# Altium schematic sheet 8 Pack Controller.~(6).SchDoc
size B; PageSetup: Record=PageOptions|CenterHorizontal=True|CenterVertical=True|PrintScale=1.09|XCorrection=1.00|YCorrection=1.00|PrintKind=0|BorderSize=5000000|LeftOffset=0|BottomOffset=0|Orientation=2|PaperLength=1000|PaperWidth=1000|Scale=100|PaperSource=15|PrintQuality=600|MediaType=1|DitherType=10|PaperKind=11x17|PrintScaleMode=1
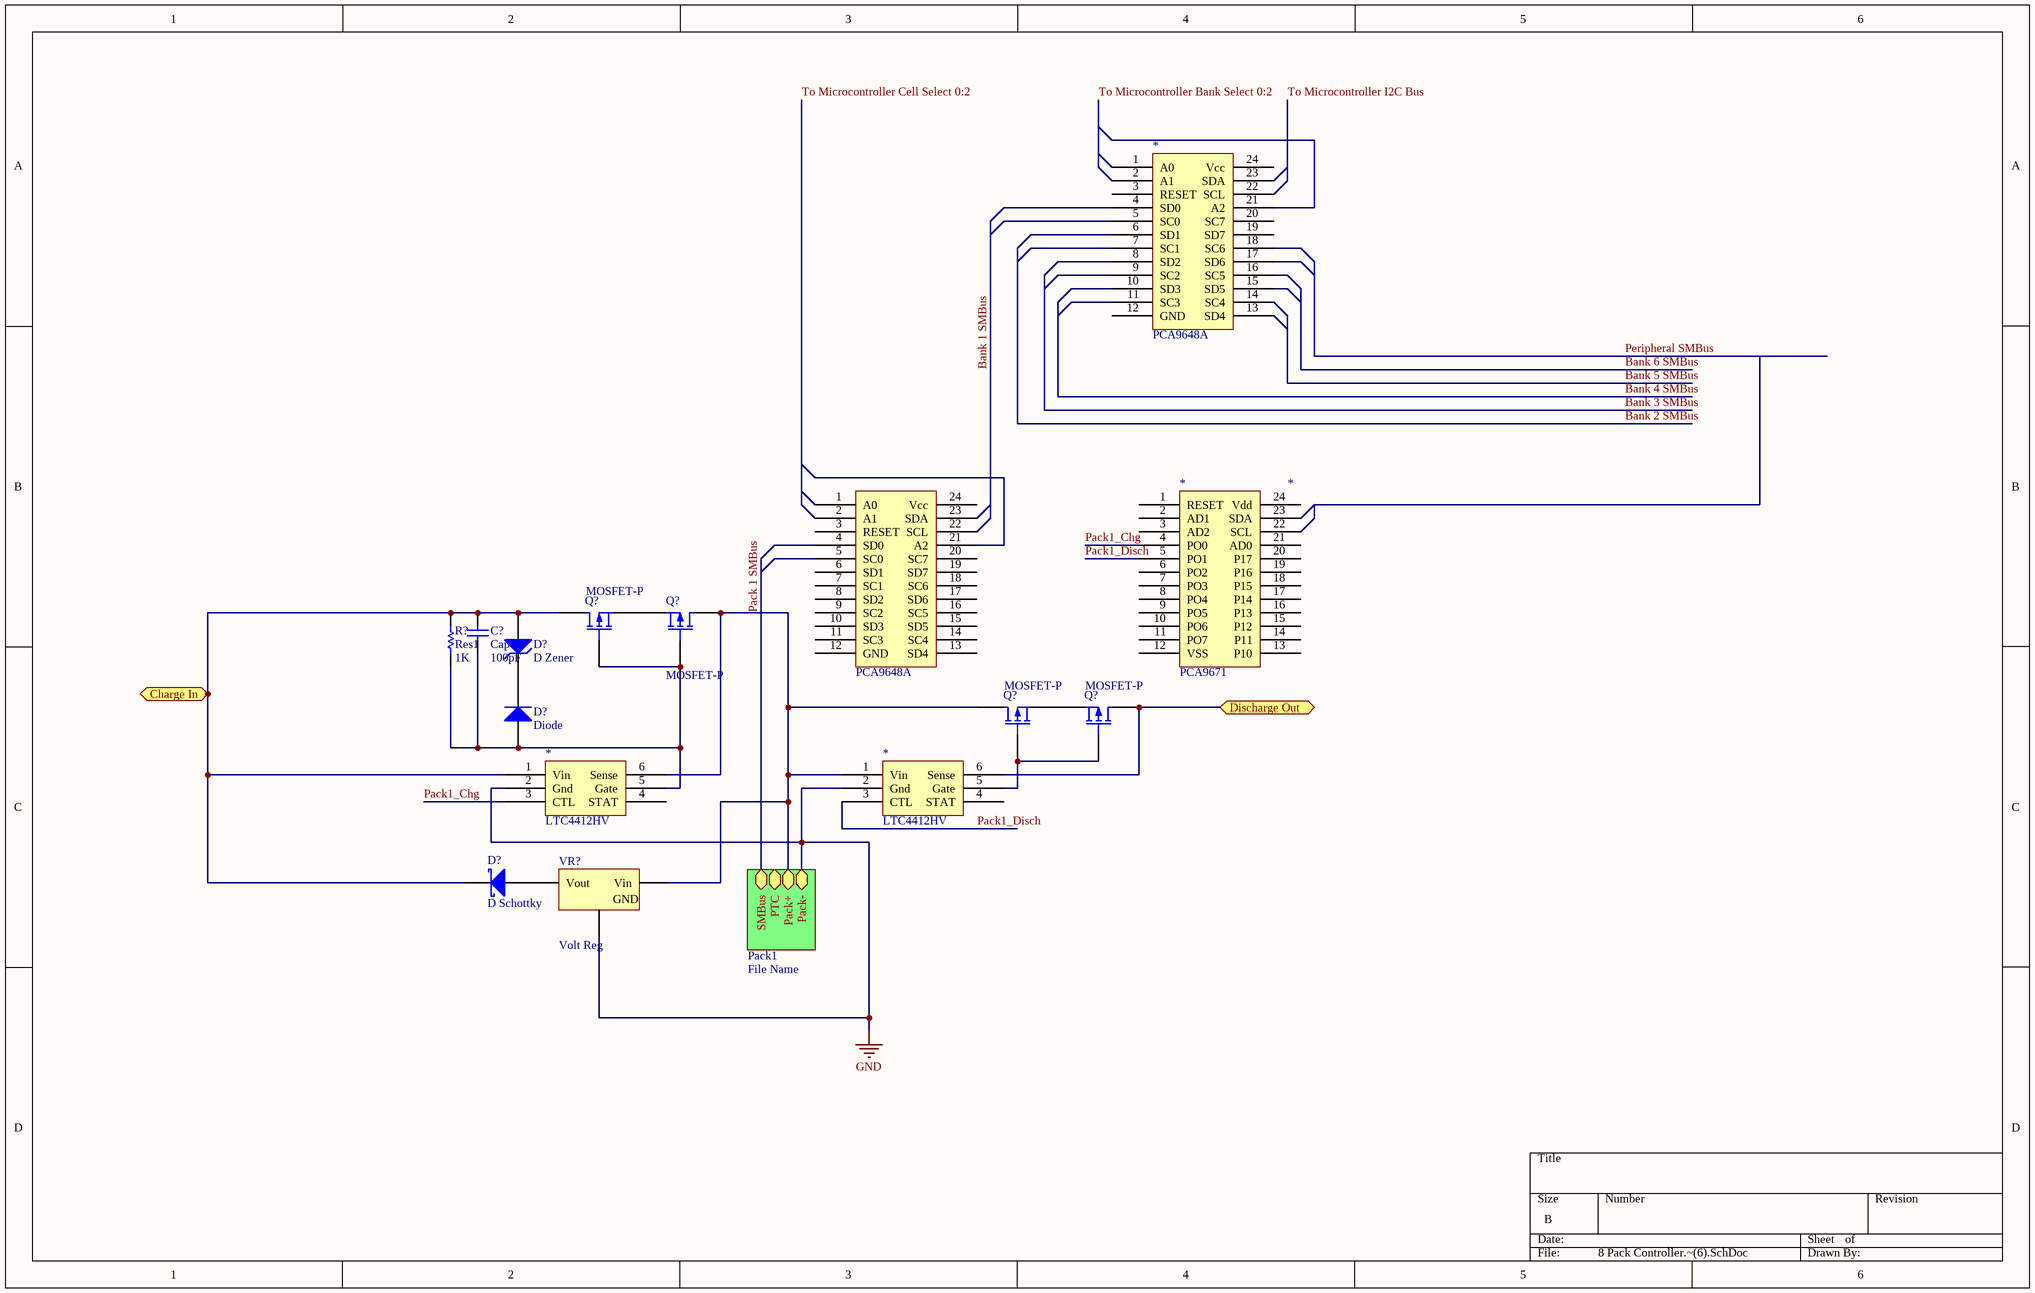
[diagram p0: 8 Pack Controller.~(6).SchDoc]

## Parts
(Parts that share a designator on the sheet are numbered #1, #2 ... from top to bottom, then left to right.)
*#1  PCA9648A
*#2  PCA9648A
*#3  PCA9671
*#4  LTC4412HV
*#5  LTC4412HV
C?  Cap  value 100pF  [RAD-0.3]
D?#1  D Zener  [DIODE-0.7]
D?#2  Diode  [DSO-C2/X3.3]
D?#3  D Schottky  [DSO-C2/X2.3]
Q?#1  MOSFET-P  [BCY-W3/B.8]
Q?#2  MOSFET-P  [BCY-W3/B.8]
Q?#3  MOSFET-P  [BCY-W3/B.8]
Q?#4  MOSFET-P  [BCY-W3/B.8]
R?  Res1  value 1K  [AXIAL-0.3]
VR?  Volt Reg  [TO254P1510-3_4N]

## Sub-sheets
Pack1 = File Name: SMBus, PTC, Pack+, Pack-

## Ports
Charge In, Discharge Out

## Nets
GND: *#4.2(Gnd) *#5.2(Gnd) VR?.2(GND) ; sheet Pack1/Pack-
Charge In: *#4.1(Vin) C?.2 D?#1.1(A) D?#3.2(K) Q?#1.1(D) R?.2 ; port Charge In
Discharge Out: *#5.6(Sense) Q?#4.1(D) ; port Discharge Out
Pack1_Chg: *#3.4(PO0) *#4.3(CTL)
Pack1_Disch: *#3.5(PO1) *#5.3(CTL)
Pack 1 SMBus: *#4.6(Sense) *#5.1(Vin) Q?#2.1(D) Q?#3.1(D) VR?.1(Vin) ; sheet Pack1/Pack+
Net*#4_5: *#4.5(Gate) C?.1 D?#2.1(A) Q?#1.2(G) Q?#2.2(G) R?.1
Net*#5_5: *#5.5(Gate) Q?#3.2(G) Q?#4.2(G)
NetD?#1_2: D?#1.2(K) D?#2.2(K)
NetD?#3_1: D?#3.1(A) VR?.3(Vout)
NetQ?#1_3: Q?#1.3(S) Q?#2.3(S)
NetQ?#3_3: Q?#3.3(S) Q?#4.3(S)

Not connected (* = marked no-connect by the designer): *#1 1(A0) 2(A1) 3(RESET) 4(SD0) 5(SC0) 6(SD1) 7(SC1) 8(SD2) 9(SC2) 10(SD3) 11(SC3) 12(GND) 13(SD4) 14(SC4) 15(SD5) 16(SC5) 17(SD6) 18(SC6) 19(SD7) 20(SC7) 21(A2) 22(SCL) 23(SDA) 24(Vcc); *#2 1(A0) 2(A1) 3(RESET) 4(SD0) 5(SC0) 6(SD1) 7(SC1) 8(SD2) 9(SC2) 10(SD3) 11(SC3) 12(GND) 13(SD4) 14(SC4) 15(SD5) 16(SC5) 17(SD6) 18(SC6) 19(SD7) 20(SC7) 21(A2) 22(SCL) 23(SDA) 24(Vcc); *#3 1(RESET) 2(AD1) 3(AD2) 6(PO2) 7(PO3) 8(PO4) 9(PO5) 10(PO6) 11(PO7) 12(VSS) 13(P10) 14(P11) 15(P12) 16(P13) 17(P14) 18(P15) 19(P16) 20(P17) 21(AD0) 22(SCL) 23(SDA) 24(Vdd); *#4 4(STAT); *#5 4(STAT)

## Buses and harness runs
bus Bank 1 SMBus
bus Bank 2 SMBus
bus Bank 3 SMBus
bus Bank 4 SMBus
bus Bank 5 SMBus
bus Bank 6 SMBus
bus Peripheral SMBus
bus To Microcontroller Bank Select 0:2
bus To Microcontroller Cell Select 0:2
bus To Microcontroller I2C Bus

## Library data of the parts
C? = Cap: Capacitor
D?#1 = D Zener: Zener Diode
D?#2 = Diode: Default Diode
D?#3 = D Schottky: Schottky Diode
Q?#1-Q?#4 = MOSFET-P: P-Channel MOSFET
R? = Res1: Resistor
VR? = Volt Reg: Voltage Regulator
